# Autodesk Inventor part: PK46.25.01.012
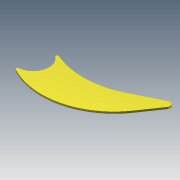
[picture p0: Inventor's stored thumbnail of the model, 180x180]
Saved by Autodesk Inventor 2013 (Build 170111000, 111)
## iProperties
Created: 2005-04
Part Number: PK46.25.01.012
Material: Steel, Mild
Document SubType Name: Modeling
Designer: salex
Manufacturer: Standard
Standards Organization: Custom
Density: 7.86 g/cm^3
Author: salex
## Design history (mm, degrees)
sketch "Эскиз1"
  geometry: L1 (511.728, 24.566)-(586.499, 133.696); L2 (561.11, 162.916)-(411.686, 88.771); A1 r 85 centre (0, 0) between (6.885, -84.721) and (52.08, 67.176); A2 r 20 centre (570, 145) between (586.499, 133.696) and (561.11, 162.916); A3 r 390 centre (190, 245) between (4.116, -97.851) and (511.728, 24.566); A4 r 7 centre (7.452, -91.698) between (6.885, -84.721) and (4.116, -97.851); A5 r 420 centre (225, 465) between (59.134, 79.14) and (411.686, 88.771); A6 r 7 centre (56.369, 72.709) between (59.134, 79.14) and (52.08, 67.176)
  constraints: 12 point on circle, 8 tangent, 6 centre point, 4 end point, 1 other
  dimensions: "d0" = 570 horizontal distance of A2.centre A1.centre; "d1" = 170 diameter of A1; "d2" = 40 diameter of A2; "d3" = 145 vertical distance of A1.centre A2.centre; "d5" = 380 horizontal distance of A3.centre A2.centre; "d7" = 420 radius of A5; "d8" = 390 radius of A3; "d9" = 100 vertical distance of A2.centre A3.centre; "d10" = 320 vertical distance of A2.centre A5.centre; "d11" = 345 horizontal distance of A5.centre A2.centre; "d12" = 14 diameter of A6; "d13" = 7 radius of A4
extrude "Выдавливание1" new body sketch "Эскиз1" distance "d14" = 10; taper "d15" = 0 deg
body "Solid1"
